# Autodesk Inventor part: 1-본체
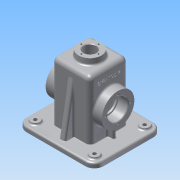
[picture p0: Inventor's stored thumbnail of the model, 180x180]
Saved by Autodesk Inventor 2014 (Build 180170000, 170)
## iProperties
Created: 2015-12
Part Number: 1-본체
Material: 알루미늄 6061
Document SubType Name: Modeling
Designer: Administrator
Density: 2.71 g/cm^3
Appearance: 알루미늄 - 평지
Mass: 789.44 g
Surface Area: 912.75 cm^2
Volume: 291.306 cm^3
Author: Administrator
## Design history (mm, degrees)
sketch "스케치1"
  geometry: L1 (65, -57.5)-(-65, -57.5); L2 (-65, -57.5)-(-65, 57.5); L3 (-65, 57.5)-(65, 57.5); L4 (65, 57.5)-(65, -57.5); L5 (65, -57.5)-(-65, 57.5); L6 (-65, -57.5)-(65, 57.5); 1 further point
  constraints: 12 end point, 2 midpoint, 2 parallel, 1 horizontal, 1 perpendicular
  dimensions: "d0" = 130 distance of L2.end L3.end; "d1" = 115 distance of L3.end L1.start
extrude "돌출1" new body sketch "스케치1" distance "d2" = 8; taper "d3" = 0 deg
sketch "스케치2"
  geometry: L1 (32.5, -32.5)-(-32.5, -32.5); L2 (-32.5, -32.5)-(-32.5, 32.5); L3 (-32.5, 32.5)-(32.5, 32.5); L4 (32.5, 32.5)-(32.5, -32.5); L5 (32.5, -32.5)-(-32.5, 32.5); L6 (-32.5, -32.5)-(32.5, 32.5); 1 further point
  constraints: 12 end point, 2 midpoint, 2 parallel, 1 horizontal, 1 perpendicular
  dimensions: "d4" = 65 distance of L2.end L3.end; "d5" = 65 distance of L3.end L1.start
extrude "돌출2" join sketch "스케치2" distance "d6" = 100; taper "d7" = 0 deg
node "작업 평면1"
sketch "스케치3"
  geometry: L1 (57.5, 8)-(-57.5, 8) reference; L2 (-57.5, 0)-(-57.5, 8) reference; L3 (57.5, 0)-(57.5, 8) reference; L4 (-47.5, 8)-(-31.379, 99.424); L5 (31.379, 99.424)-(47.5, 8); L6 (-31.379, 99.424)-(31.379, 99.424); L7 (-47.5, 8)-(47.5, 8); 1 further point
  constraints: 8 end point, 2 point on line, 1 collinear, 1 perpendicular
  dimensions: "d9" = 10 deg angle of L2 L4; "d10" = 10 distance from line of L4.start L2; "d11" = 10 distance of L1.start L5.end; "d12" = 10 deg angle of L3 L5; "d13" = 62.75886 distance of L4.end L5.start
extrude "돌출3" join sketch "스케치3" stored distance "d14" = 10; taper "d15" = 0 deg
fillet "모깎기1" dims "d16" = 8
fillet "모깎기2" dims "d17" = 8
node "작업 평면2"
sketch "스케치5"
  geometry: L1 (-8, -33)-(-8, 82) reference; C1 r 27.5 at (45, 24.5); 2 further points
  constraints: 1 centre point, 1 horizontal alignment, 1 midpoint
  dimensions: "d23" = 53 distance from line of C1.centre L1; "d24" = 55 diameter of C1
extrude "돌출5" join sketch "스케치5" stored distance "d25" = 10; taper "d26" = 0 deg
node "작업 평면3"
node "작업 평면4"
sketch "스케치6"
  geometry: L1 (24.5, 32.5)-(5, 32.5) reference; L2 (-5, 32.5)-(-24.5, 32.5) reference; L3 (5, -32.5)-(24.5, -32.5) reference; L4 (-24.5, -32.5)-(-5, -32.5) reference; L5 (32.5, -24.5)-(32.5, 24.5) reference; L6 (-32.5, 24.5)-(-32.5, -24.5) reference; L7 (27.5, 27.5)-(-27.5, 27.5); L8 (-27.5, 27.5)-(-27.5, -27.5); L9 (-27.5, -27.5)-(27.5, -27.5); L10 (27.5, -27.5)-(27.5, 27.5); L11 (27.5, 27.5)-(-27.5, -27.5); L12 (-27.5, 27.5)-(27.5, -27.5); 1 further point
  constraints: 12 end point, 2 midpoint, 2 parallel, 1 horizontal, 1 perpendicular
  dimensions: "d27" = 55 distance of L9.end L7.start; "d28" = 55 distance of L8.end L9.end
extrude "돌출6" cut sketch "스케치6" distance "d29" = 103; taper "d30" = 0 deg
fillet "모깎기5" dims "d38" = 3
fillet "모깎기6" dims "d39" = 3
fillet "모깎기7" dims "d40" = 3
hole "구멍1" diameter "d43" = 30; stored, may be unused: countersink angle "d47" = 90 deg, drill point angle "d49" = 118 deg; dims "d41" = 10, "d42" = 10, "d44" = 6, "d45" = 35, "d46" = 17, "d48" = 8
sketch "스케치8" dims "d51" = 42
  geometry: C1 r 17.5 at (0, 0) reference; C2 r 27.5 at (0, 0) reference; 6 further points
  constraints: 2 vertical alignment, 1 coincident, 7 other
  dimensions: "d54" = 360 deg dimension on C1.centre point (0, 21) (derived)
hole "구멍2" sketch "스케치8" at (0, 21), (-21, 0), (0, -21), (21, 0) diameter "d56" = 3.242; stored, may be unused: countersink angle "d60" = 90 deg, drill point angle "d62" = 118 deg; dims "d57" = 8, "d58" = 35, "d59" = 17, "d61" = 10
fillet "모깎기8" dims "d63" = 0.3
sketch "스케치9"
  geometry: L1 (-27.5, -24.5)-(-27.5, 24.5) reference; L2 (-24.5, 27.5)-(24.5, 27.5) reference; L3 (27.5, 24.5)-(27.5, -24.5) reference; L4 (24.5, -27.5)-(-24.5, -27.5) reference; L5 (-60, -52.5)-(60, -52.5); L6 (60, -52.5)-(60, 52.5); L7 (60, 52.5)-(-60, 52.5); L8 (-60, 52.5)-(-60, -52.5); L9 (-60, -52.5)-(60, 52.5); L10 (60, -52.5)-(-60, 52.5); A1 r 3 centre (-24.5, 24.5) between (-24.5, 27.5) and (-27.5, 24.5) reference; A2 r 3 centre (24.5, 24.5) between (27.5, 24.5) and (24.5, 27.5) reference; A3 r 3 centre (24.5, -24.5) between (24.5, -27.5) and (27.5, -24.5) reference; A4 r 3 centre (-24.5, -24.5) between (-27.5, -24.5) and (-24.5, -27.5) reference; 1 further point
  constraints: 12 end point, 2 midpoint, 2 parallel, 1 horizontal, 1 perpendicular
  dimensions: "d66" = 120 distance of L6.end L7.end; "d67" = 105 distance of L5.end L6.end
extrude "돌출8" join sketch "스케치9" distance "d68" = 2; taper "d69" = 0 deg
fillet "모깎기11" dims "d70" = 15
sketch "스케치10"
  geometry: C1 r 7.5 at (-50, 42.5); C2 r 7.5 at (50, 42.5); C3 r 7.5 at (50, -42.5); C4 r 7.5 at (-50, -42.5); A1 r 15 centre (-50, -42.5) between (-65, -42.5) and (-50, -57.5) reference; A2 r 15 centre (50, -42.5) between (50, -57.5) and (65, -42.5) reference; A3 r 15 centre (50, 42.5) between (65, 42.5) and (50, 57.5) reference; A4 r 15 centre (-50, 42.5) between (-50, 57.5) and (-65, 42.5) reference; 1 further point
  constraints: 4 centre point, 4 coincident, 3 equal radius
  dimensions: "d71" = 15 diameter of C1
extrude "돌출9" join sketch "스케치10" distance "d72" = 3; taper "d73" = 0 deg
fillet "모깎기12" dims "d74" = 3
sketch "스케치11"
  geometry: C1 r 7.5 at (0, 0) reference; C2 r 7.5 at (-100, 85) reference; C3 r 7.5 at (0, 85) reference; C4 r 7.5 at (-100, 0) reference; 5 further points
  constraints: 4 coincident
hole "구멍3" sketch "스케치11" at (-100, 85), (0, 85), (0, 0), (-100, 0) diameter "d75" = 6; stored, may be unused: countersink angle "d79" = 90 deg, drill point angle "d81" = 0 deg; dims "d76" = 8, "d77" = 35, "d78" = 17, "d80" = 10
sketch "스케치12"
  geometry: C1 r 20 at (0, 0); 1 further point
  constraints: 1 centre point, 1 coincident
  dimensions: "d82" = 40 diameter of C1
extrude "돌출10" join sketch "스케치12" distance "d83" = 10; taper "d84" = -5 deg
fillet "모깎기13" dims "d85" = 3
hole "구멍4" diameter "d88" = 21; stored, may be unused: countersink angle "d92" = 90 deg, drill point angle "d94" = 0 deg; dims "d86" = 10, "d87" = 10, "d89" = 8, "d90" = 35, "d91" = 17, "d93" = 10
sketch "스케치13" dims "d95" = 29
  geometry: C1 r 10.5 at (0, 0) reference; C2 r 19.125 at (0, 0) reference; 5 further points
  constraints: 2 vertical alignment, 1 coincident, 7 other
  dimensions: "d98" = 360 deg dimension on C1.centre point (0, 14.5) (derived)
hole "구멍5" sketch "스케치13" at (0, 14.5), (-14.5, 0), (0, -14.5), (14.5, 0) diameter "d100" = 2.459; stored, may be unused: countersink angle "d104" = 90 deg, drill point angle "d106" = 118 deg; dims "d101" = 7, "d102" = 35, "d103" = 17, "d105" = 9
node "작업 평면5"
sketch "스케치15"
  geometry: L1 (-32.5, -24.5)-(-32.5, 24.5) reference; L2 (-47.5, -27.5)-(-47.5, 27.5) reference; L3 (-42.5, 3)-(-32.5, 3); L4 (-32.5, 3)-(-32.5, -3); L5 (-32.5, -3)-(-42.5, -3); L6 (-42.5, -3)-(-42.5, 3); L7 (-42.5, 3)-(-32.5, -3); L8 (-32.5, 3)-(-42.5, -3); 4 further points
  constraints: 12 end point, 4 midpoint, 2 parallel, 1 collinear, 1 horizontal, 1 horizontal alignment, 1 perpendicular
  dimensions: "d112" = 6 distance of L5.end L3.start; "d113" = 10 distance between parallel lines of L1 L6
extrude "돌출12" join sketch "스케치15" stored distance "d114" = 10; taper "d115" = 0 deg
node "작업 평면6"
fillet "모깎기14" dims "d116" = 3
fillet "모깎기15" dims "d117" = 1
fillet "모깎기16" dims "d118" = 3
chamfer "모따기1" distance "d119" = 1; stored, may be unused: second distance "d120" = 2, angle "d121" = 45 deg
fillet "모깎기17" dims "d122" = 10
sketch "스케치16"
  geometry: L1 (-18, 5.375)-(-18, 43.625) reference; A1 r 30.5 centre (47, 24.5) between (28.834, 49) and (28.834, 0) reference; 2 further points
  constraints: 1 horizontal alignment, 1 other
  dimensions: "d123" = 26 distance from line of point (8, 24.5) L1
feature "엠보싱1" sketch "스케치16" dims "d124" = 0.5, "d125" = 0
node "솔리드1"
mirror "대칭1"
mirror "대칭2"
mirror "대칭4"
node "투영된 루프1"
node "투영된 루프2"
node "투영된 루프3"
other parameters: "d8" = 0, "d22" = 15, "d33" = 0
